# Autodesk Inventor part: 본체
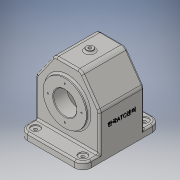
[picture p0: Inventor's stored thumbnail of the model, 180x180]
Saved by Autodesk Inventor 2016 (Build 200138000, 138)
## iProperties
Created: 2022-12
Part Number: 본체
Material: 일반
Document SubType Name: Modeling
Designer: Windows7
Density: 1 g/cm^3
Appearance: 기본값
Mass: 347.118 g
Surface Area: 1065.22 cm^2
Volume: 347.118 cm^3
Author: Windows7
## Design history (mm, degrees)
sketch "스케치5"
  geometry: L1 (55, -65)-(-55, -65); L2 (-55, -65)-(-55, 57); L3 (-55, 57)-(55, 57); L4 (55, 57)-(55, -65); L5 (55, -65)-(-55, 57); L6 (-55, -65)-(55, 57); 3 further points
  constraints: 12 end point, 3 midpoint, 2 parallel, 1 horizontal, 1 perpendicular, 1 vertical alignment
  dimensions: "d9" = 122 distance between parallel lines of L1 L3; "d10" = 65 distance from line of L1 point (0, 0); "d11" = 110 distance between parallel lines of L4 L2
extrude "돌출2" new body sketch "스케치5" stored distance "d12" = 77; taper "d13" = 0 deg
sketch "스케치6"
  geometry: L1 (55, 12)-(23.491, 57); L2 (55, 57)-(-55, 57) reference; L3 (55, -65)-(55, 57) reference; L4 (0, -89.4)-(0, 81.4) reference; L5 (-55, 12)-(-23.491, 57); L6 (-55, -65)-(55, -65) reference; L7 (55, -65)-(55, 57) reference; L8 (55, 57)-(-55, 57) reference; L9 (-55, 57)-(-55, -65) reference; 1 further point
  constraints: 4 end point, 2 point on line, 2 symmetric about line
  dimensions: "d14" = 35 deg angle of L3 L1; "d15" = 77 distance of L3.start L1.start
extrude "돌출3" cut sketch "스케치6" stored distance "d16" = 77; taper "d17" = 0 deg
fillet "모깎기2" dims "d18" = 3
fillet "모깎기3" dims "d19" = 10
feature "쉘1" dims "d20" = 5
sketch "스케치7"
  geometry: C1 r 37.5 at (0, 0); 1 further point
  constraints: 1 centre point, 1 coincident
  dimensions: "d21" = 75 diameter of C1
extrude "돌출4" join sketch "스케치7" distance "d22" = 5; taper "d23" = 0 deg
fillet "모깎기4" dims "d33" = 3
sketch "스케치8"
  geometry: L1 (-19.5, 27)-(-19.5, -27); L2 (-19.5, 27)-(-33.5, 41); L3 (-33.5, 49.868)-(-33.5, 11.715) reference; L4 (-19.5, -27)-(-33.5, -41); L5 (-33.5, 8.847)-(-33.5, -65) reference; L6 (-43.5, 37.5)-(-43.5, -37.5) reference; L7 (-33.5, 41)-(-33.5, -41); L8 (-19.5, 0)-(-33.5, 0); 1 further point
  constraints: 10 end point, 2 midpoint, 2 point on line, 1 collinear, 1 horizontal alignment, 1 vertical
  dimensions: "d37" = 54 distance of L1.start L1.end; "d38" = 135 deg angle of L5 L4; "d39" = 135 deg angle of L2 L3; "d40" = 24 distance between parallel lines of L1 L6
revolve "회전1" sketch "스케치8" stored, may be unused: angle "d41" = 90 deg
fillet "모깎기5" dims "d44" = 3
fillet "모깎기6" dims "d45" = 3
hole "구멍2" diameter "d48" = 40; stored, may be unused: countersink angle "d52" = 90 deg, drill point angle "d54" = 118 deg; dims "d46" = 10, "d47" = 10, "d49" = 6, "d50" = 4, "d51" = 2, "d53" = 8
node "작업 평면3"
sketch "스케치10"
  geometry: C1 r 6 at (18.285, -35.5); 1 further point
  constraints: 1 centre point, 1 coincident
  dimensions: "d57" = 12 diameter of C1
extrude "돌출6" join sketch "스케치10" distance "d58" = 5; taper "d59" = 0 deg
fillet "모깎기7" dims "d60" = 3
hole "구멍3" diameter "d63" = 5.188; stored, may be unused: countersink angle "d67" = 90 deg, drill point angle "d69" = 118 deg; dims "d61" = 10, "d62" = 10, "d64" = 9, "d65" = 4, "d66" = 2, "d68" = 16
sketch "스케치11"
  geometry: L1 (0, 0)-(0, 29)
  constraints: 2 end point, 1 vertical
  dimensions: "d70" = 29 distance of L1.start L1.end
hole "구멍4" sketch "스케치11" at (0, 29) diameter "d71" = 2.459; stored, may be unused: countersink angle "d75" = 90 deg, drill point angle "d77" = 118 deg; dims "d72" = 6, "d73" = 4, "d74" = 2, "d76" = 8
sketch "스케치12"
  geometry: C1 r 31 at (0, 0); 1 further point
  constraints: 1 centre point, 1 coincident
  dimensions: "d81" = 62 diameter of C1
extrude "돌출7" join sketch "스케치12" distance "d82" = 10; taper "d83" = 0 deg
hole "구멍5" diameter "d86" = 40; stored, may be unused: countersink angle "d90" = 90 deg, drill point angle "d92" = 118 deg; dims "d84" = 10, "d85" = 10, "d87" = 6, "d88" = 4, "d89" = 2, "d91" = 8
sketch "스케치13"
  geometry: L1 (0, 0)-(0, -26); L2 (-18.285, -49)-(18.285, -49) reference
  constraints: 2 end point, 1 perpendicular
  dimensions: "d93" = 26 distance of L1.start L1.end
hole "구멍6" sketch "스케치13" at (0, -26) diameter "d94" = 2.459; stored, may be unused: countersink angle "d98" = 90 deg, drill point angle "d100" = 118 deg; dims "d95" = 6, "d96" = 4, "d97" = 2, "d99" = 8
fillet "모깎기8" dims "d104" = 3
sketch "스케치14"
  geometry: L1 (2, -69)-(2, -8) reference; L2 (5, -5)-(99, -5) reference; L3 (102, -8)-(102, -69) reference; L4 (99, -72)-(5, -72) reference; L5 (0, 0)-(104, 0) reference; L6 (-3, -3)-(-3, -74) reference; L7 (104, -77)-(0, -77) reference; L8 (107, -74)-(107, -3) reference; L9 (107, -105.5)-(-3, -105.5); L10 (-3, -105.5)-(-3, 28.5); L11 (-3, 28.5)-(107, 28.5); L12 (107, 28.5)-(107, -105.5); L13 (107, -105.5)-(-3, 28.5); L14 (-3, -105.5)-(107, 28.5); C1 r 2.594 at (52, -38.5) reference; A1 r 3 centre (5, -8) between (5, -5) and (2, -8) reference; A2 r 3 centre (99, -8) between (102, -8) and (99, -5) reference; A3 r 3 centre (99, -69) between (99, -72) and (102, -69) reference; A4 r 3 centre (5, -69) between (2, -69) and (5, -72) reference; A5 r 3 centre (104, -3) between (107, -3) and (104, 0) reference; A6 r 3 centre (0, -3) between (0, 0) and (-3, -3) reference; A7 r 3 centre (0, -74) between (-3, -74) and (0, -77) reference; A8 r 3 centre (104, -74) between (104, -77) and (107, -74) reference; 1 further point
  constraints: 12 end point, 2 midpoint, 2 parallel, 1 horizontal, 1 perpendicular
  dimensions: "d105" = 110 distance of L10.end L11.end; "d106" = 134 distance of L9.end L10.end
extrude "돌출8" join sketch "스케치14" distance "d107" = 12; taper "d108" = 0 deg
fillet "모깎기9" dims "d109" = 14
fillet "모깎기10" dims "d110" = 3
hole "구멍7" diameter "d113" = 5.5; stored, may be unused: countersink angle "d117" = 90 deg, drill point angle "d119" = 118 deg; dims "d111" = 10, "d112" = 10, "d114" = 6, "d115" = 4, "d116" = 2, "d118" = 8
hole "구멍8" diameter "d122" = 15; stored, may be unused: countersink angle "d126" = 90 deg, drill point angle "d128" = 0 deg; dims "d120" = 10, "d121" = 10, "d123" = 6, "d124" = 4, "d125" = 2, "d127" = 2
node "작업 평면4"
sketch "스케치15"
  geometry: L1 (0, -3)-(58.847, -3) reference; L2 (73.847, -17.5)-(73.847, -31.5) reference; 2 further points
  constraints: 1 other
  dimensions: "d130" = 38.5 distance from line of L1 point (23.847, 35.5); "d131" = 50 distance from line of L2 point (23.847, 35.5)
feature "엠보싱1" sketch "스케치15" dims "d132" = 0.5, "d133" = 0
chamfer "모따기2" distance "d134" = 1; stored, may be unused: second distance "d135" = 2, angle "d136" = 45 deg
sketch "스케치16"
  geometry: L1 (0, 84.057)-(-91.395, 84.057); L2 (-91.395, 84.057)-(-91.395, -90.061); L3 (-91.395, -90.061)-(0, -90.061); L4 (0, -90.061)-(0, 84.057); 1 further point
  constraints: 8 end point, 2 parallel, 1 horizontal, 1 perpendicular
extrude "돌출9" cut sketch "스케치16" stored distance "d137" = 12; taper "d138" = 0 deg
node "솔리드2"
mirror "대칭1"
pattern_circular "원형 패턴1" dims angle "d79" = 360 deg
pattern_circular "원형 패턴2" dims angle "d102" = 360 deg
mirror "대칭2"
mirror "대칭3"
node "투영된 루프1"
node "투영된 루프2"
other parameters: "d56" = 4, "d129" = 71.25
